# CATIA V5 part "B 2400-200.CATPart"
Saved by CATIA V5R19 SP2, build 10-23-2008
Part number: B 2400-200
Bounding box of the stored display mesh (mm): x -37.351 to 37.351, y -37.351 to 37.351, z 0 to 510
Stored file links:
  C:\Users\Bora\Desktop\3D Katı model\B serisi\B 2400\B 2400-200.CATPart
  C:\Program Files\Dassault Systemes\B19\intel_a\reffiles\standard\MetricThickPitch.txt
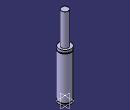
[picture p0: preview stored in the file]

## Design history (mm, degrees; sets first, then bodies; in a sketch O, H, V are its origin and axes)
Body1 (main body)
  Sketch1 on yz-plane, origin (0, 0, 0), H (0, 1, 0), V (0, 0, 1)
    point P3 (22.5, 509)
    point P5 (22.5, 509)
    point P10 (37.5, 286.5)
    point P11 (37.5, 291.5)
    point P13 (37.5, 291.5)
    point P14 (37.5, 286.5)
    line L1 (37.5, 0) -> (37.5, 8)
    line L2 (22.5, 509) -> (22.5, 307)
    arc A1 centre (21.5, 509) radius 1 from (22.5, 509) to (21.5, 510) ccw
    line L3 (33.5, 13) -> (33.5, 8)
    line L4 (37.5, 13) -> (37.5, 286.5)
    line L5 (37.5, 291.5) -> (37.5, 307)
    arc A2 centre (37.5, 289) radius 2.5 from (37.5, 291.5) to (37.5, 286.5) ccw
    line L6 (21.5, 510) -> (0, 510)
    point P15 (0, 510)
    line L7 (22.5, 307) -> (37.5, 307)
    line L8 (0, 0) -> (37.5, 0)
    line L9 (33.5, 13) -> (37.5, 13)
    line L10 (33.5, 8) -> (37.5, 8)
    coincidence: P15 V, P3 P5, P10 P14, P11 P13
    tangency: L6 A1
    horizontal: L7 H, L8 H, L9 H, L10 H
  Shaft1: profile Sketch1, axis Sketch1.V, angle 360
  Sketch2 on face of Shaft1 from Sketch1.L8, origin (0, 0, 0), H (1, 0, 0), V (0, -1, 0)
    point P1 (20, 0)
    distance P1 V = 20
  Hole1: placed by Sketch2, at (20, 0, 0) direction (0, 0, 1), diameter 6.647, depth 13, threaded "M8", thread diameter 8, thread depth 13, pitch 1.25
  CircPattern1: of Hole1, instances 4, angular step 90, axis from xy-plane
